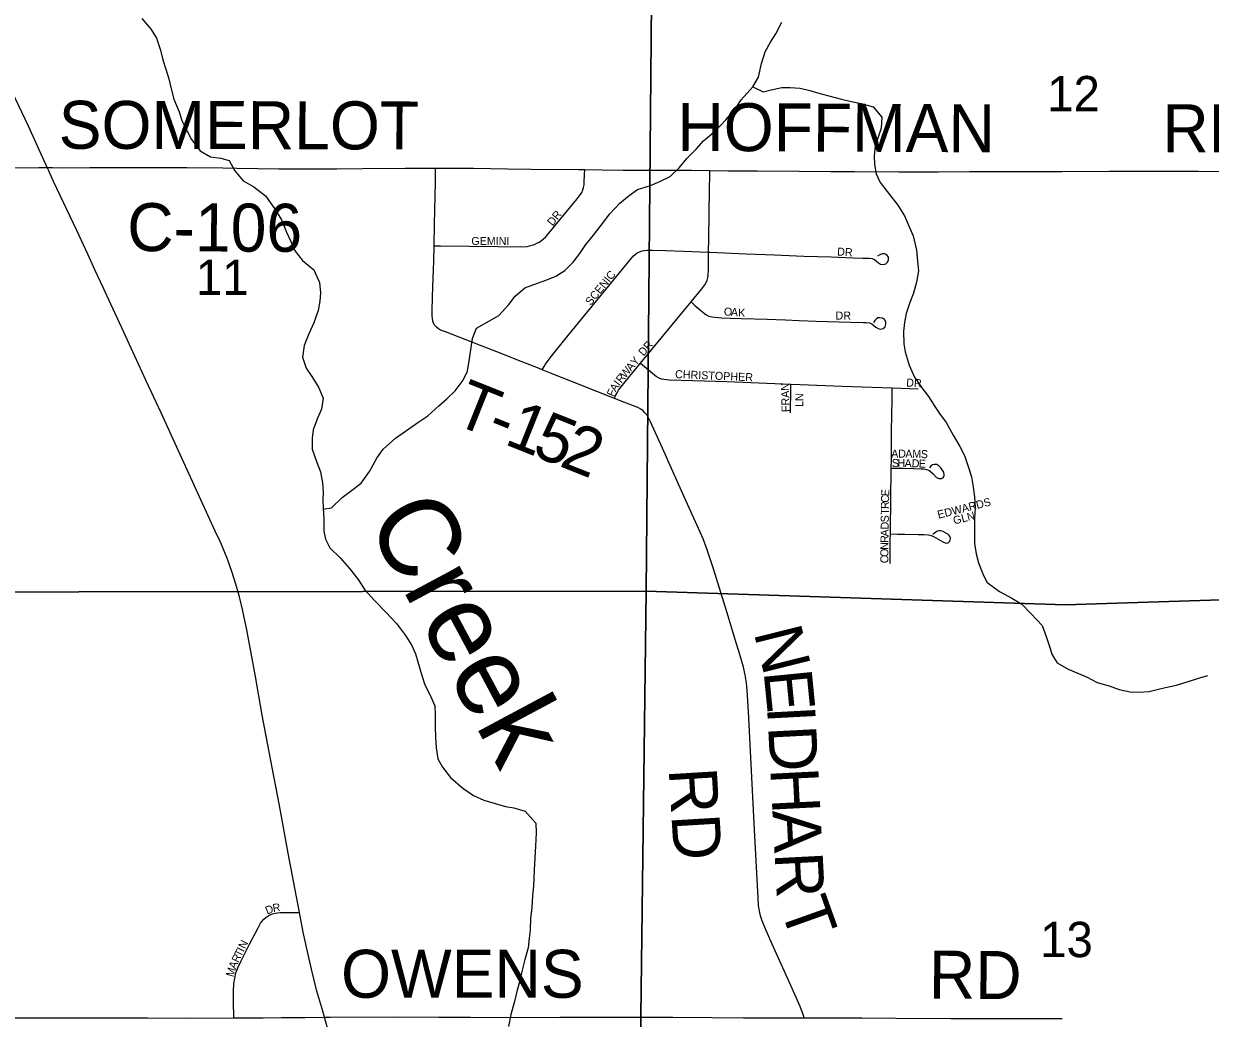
# Model space of a CAD drawing. Extents: x -9.1 to 34, y -3.1 to 22.
# Drawn here: x 6.461 to 7.865, y 15.245 to 16.422 of the extents above; entities that cross this region are included whole.
import ezdxf

# ---------------------------------------------------------------- set-up
doc = ezdxf.new("R2010")
doc.units = 0
for name, color, linetype in [('GM_X_County_Road', 7, 'Continuous'), ('GM_X_County_Road_Text', 7, 'Continuous'), ('GM_X_Minor_River', 7, 'Continuous'), ('GM_X_Minor_River_Text', 7, 'Continuous'), ('GM_X_Section', 7, 'Continuous'), ('GM_X_Section_Text', 7, 'Continuous'), ('GM_X_State_Route', 7, 'Continuous'), ('GM_X_Township_Road', 7, 'Continuous'), ('GM_X_Township_Road_Text', 7, 'Continuous'), ('GM_X_Township_Subdivision', 7, 'Continuous'), ('GM_X_Township_Subdivision_Text', 7, 'Continuous')]:
    doc.layers.add(name, color=color, linetype=linetype)

msp = doc.modelspace()

# ---------------------------------------------------------------- linework, layer by layer
at = {"layer": 'GM_X_County_Road'}
for points in [[(6.4495, 16.2516), (6.4791, 16.2519), (6.4892, 16.2518)], [(6.4892, 16.2518), (6.4954, 16.2517), (6.5082, 16.2516)], [(6.5082, 16.2516), (6.5082, 16.2516), (6.5394, 16.2518), (6.5643, 16.2519), (6.5953, 16.2519), (6.6544, 16.2518), (6.697, 16.2514)], [(6.697, 16.2514), (6.7134, 16.2512), (6.7632, 16.2505), (6.7943, 16.2503), (6.8316, 16.2505), (6.8626, 16.2507), (6.9124, 16.2513), (6.9372, 16.2512), (6.9485, 16.2512)], [(6.9485, 16.2512), (6.9932, 16.251), (7.0336, 16.2503), (7.0615, 16.25), (7.1175, 16.2495), (7.125, 16.2494)], [(7.125, 16.2494), (7.1454, 16.249), (7.1703, 16.2489), (7.2138, 16.2489), (7.2511, 16.2486), (7.2729, 16.2483)], [(7.2729, 16.2483), (7.2946, 16.248), (7.3288, 16.2479), (7.3785, 16.2474), (7.4159, 16.2473), (7.4438, 16.2471), (7.4967, 16.2468), (7.5433, 16.2469), (7.5806, 16.2471), (7.6148, 16.2473), (7.6459, 16.2472), (7.6894, 16.2473), (7.7453, 16.2476), (7.7764, 16.2474), (7.8199, 16.2477), (7.851, 16.2477), (7.9224, 16.2469), (7.9473, 16.2474), (7.9655, 16.2476)], [(5.9245, 15.2457), (5.9397, 15.2456), (5.9676, 15.2455), (5.9832, 15.2453), (6.0049, 15.2451), (6.0267, 15.2453), (6.0577, 15.2453), (6.1261, 15.245), (6.1758, 15.245), (6.2255, 15.2453), (6.2815, 15.2456), (6.3436, 15.2456), (6.3778, 15.2455), (6.4182, 15.2454), (6.4617, 15.2453), (6.5332, 15.2454), (6.6078, 15.2452), (6.6575, 15.245), (6.71, 15.2453)], [(6.71, 15.2453), (6.7445, 15.2455), (6.7663, 15.2457), (6.7942, 15.2457), (6.817, 15.246)], [(6.817, 15.246), (6.8242, 15.246), (6.8997, 15.2465), (6.9525, 15.2462), (6.9611, 15.2462)], [(6.9611, 15.2462), (6.9898, 15.246), (7.0426, 15.2459), (7.0954, 15.2463), (7.1389, 15.2462), (7.1917, 15.2463), (7.1944, 15.2463)], [(7.1944, 15.2463), (7.229, 15.246), (7.2756, 15.2458), (7.3128, 15.2454), (7.3377, 15.2454), (7.378, 15.2454), (7.3847, 15.2454)], [(7.3847, 15.2454), (7.4215, 15.2455), (7.4526, 15.2453), (7.4929, 15.2451), (7.5582, 15.2447), (7.6203, 15.2445), (7.6576, 15.2445), (7.6897, 15.2447)]]:
    msp.add_lwpolyline(points, dxfattribs=at)
at = {"layer": 'GM_X_Minor_River'}
for points in [[(6.6009, 16.4281), (6.6121, 16.4151), (6.6184, 16.4048), (6.6231, 16.3907), (6.626, 16.3793), (6.6296, 16.3682), (6.6328, 16.3568), (6.6357, 16.345), (6.6389, 16.3329), (6.6452, 16.3176), (6.6484, 16.3077), (6.6547, 16.2948), (6.6599, 16.2852), (6.6699, 16.2718), (6.6823, 16.2644), (6.6944, 16.2631), (6.7042, 16.26), (6.7109, 16.2481), (6.7209, 16.2362), (6.7337, 16.2292), (6.7472, 16.2184), (6.758, 16.2035), (6.7661, 16.1898), (6.7723, 16.1753), (6.7771, 16.1642), (6.7823, 16.1528), (6.7912, 16.1417), (6.8043, 16.1309), (6.8113, 16.1156), (6.8122, 16.1035), (6.8117, 16.0936), (6.8097, 16.0827), (6.8046, 16.068), (6.7987, 16.0551), (6.7932, 16.0412), (6.7911, 16.0272), (6.7955, 16.0143), (6.8022, 16.0047), (6.8099, 15.9917), (6.8154, 15.9787), (6.8134, 15.9659), (6.8087, 15.955), (6.8039, 15.9414), (6.8026, 15.9315), (6.8025, 15.9183), (6.8076, 15.9038), (6.8123, 15.8916), (6.8148, 15.8787), (6.8154, 15.8677), (6.8153, 15.8582), (6.8155, 15.8487), (6.8165, 15.8355), (6.8163, 15.8215), (6.8184, 15.8119), (6.8236, 15.8016), (6.8355, 15.7897), (6.8467, 15.7771), (6.8571, 15.7644), (6.8649, 15.7518), (6.8761, 15.7395), (6.8895, 15.7257), (6.9022, 15.7123), (6.913, 15.6981), (6.9204, 15.6862), (6.9248, 15.6763), (6.9274, 15.6668), (6.931, 15.6546), (6.9353, 15.6406), (6.9431, 15.6253), (6.9475, 15.6146), (6.9481, 15.6036), (6.9479, 15.5904), (6.9484, 15.5771)], [(6.8156, 15.8473), (6.8254, 15.849), (6.838, 15.8613), (6.8476, 15.8684), (6.8606, 15.8784), (6.8703, 15.892), (6.8792, 15.9078), (6.8866, 15.9186), (6.9011, 15.9317), (6.9168, 15.9425), (6.9287, 15.9507), (6.9394, 15.9581), (6.9524, 15.9697), (6.962, 15.9782), (6.9716, 15.9876), (6.9813, 16), (6.9863, 16.0109), (6.9884, 16.023), (6.9901, 16.0362), (6.9922, 16.0495), (6.9969, 16.0619), (7.0125, 16.0704), (7.0232, 16.0767), (7.0352, 16.0898), (7.0425, 16.0996), (7.054, 16.1096), (7.0692, 16.1151), (7.0803, 16.1191), (7.0909, 16.1231), (7.1016, 16.1298), (7.1112, 16.1399), (7.1193, 16.15), (7.1263, 16.1609), (7.1352, 16.1718), (7.1471, 16.1872), (7.1548, 16.1969), (7.1664, 16.2097), (7.1775, 16.2186), (7.1874, 16.2257), (7.2027, 16.2304), (7.2137, 16.2352), (7.2259, 16.2414), (7.2367, 16.2515), (7.2459, 16.2624), (7.2567, 16.2736), (7.2655, 16.2833), (7.2801, 16.2956), (7.292, 16.3084), (7.3024, 16.3207), (7.3101, 16.332), (7.324, 16.3473), (7.3306, 16.359), (7.3342, 16.3749), (7.3386, 16.3888), (7.3448, 16.4001), (7.351, 16.4103), (7.358, 16.4238)], [(7.324, 16.3473), (7.336, 16.3415), (7.3455, 16.344), (7.3581, 16.3465), (7.3679, 16.3467), (7.38, 16.3458), (7.3914, 16.343), (7.4019, 16.3398), (7.4136, 16.3366), (7.4287, 16.3326), (7.4385, 16.3306), (7.4521, 16.3278), (7.4661, 16.3238), (7.4765, 16.3115), (7.4756, 16.2986), (7.4724, 16.2888), (7.4685, 16.2771), (7.4675, 16.2658), (7.4678, 16.2555), (7.4699, 16.2445), (7.4743, 16.2342), (7.4855, 16.2201), (7.4955, 16.2074), (7.5033, 16.1948), (7.5092, 16.1807), (7.5136, 16.1712), (7.5175, 16.1541), (7.5188, 16.1411), (7.5198, 16.1294), (7.5174, 16.1162), (7.5138, 16.1033), (7.5094, 16.092), (7.5051, 16.0792), (7.5031, 16.0686), (7.5021, 16.0576), (7.5023, 16.0432), (7.5041, 16.0337), (7.5088, 16.0181), (7.515, 16.0036), (7.5236, 15.991), (7.5318, 15.981), (7.5384, 15.9703), (7.5447, 15.9608), (7.5525, 15.9501), (7.561, 15.9352), (7.5688, 15.9218), (7.5743, 15.9111), (7.5787, 15.8981), (7.5827, 15.8856), (7.5841, 15.8761), (7.5861, 15.862), (7.5867, 15.8491), (7.5862, 15.8363), (7.586, 15.8215), (7.5861, 15.8067), (7.5879, 15.7946), (7.5907, 15.7839), (7.5959, 15.7709), (7.6006, 15.761), (7.6156, 15.7502), (7.6303, 15.7421), (7.6419, 15.7351), (7.6528, 15.7239), (7.6662, 15.7097), (7.671, 15.6968), (7.6739, 15.6873), (7.6779, 15.6751), (7.6838, 15.6655), (7.6969, 15.6581), (7.709, 15.6531), (7.7195, 15.6487), (7.7312, 15.6425), (7.7455, 15.6385), (7.7572, 15.6342), (7.7704, 15.6314), (7.7806, 15.6308), (7.7928, 15.6318), (7.8053, 15.6347), (7.8156, 15.6372), (7.8251, 15.6393), (7.8388, 15.6433), (7.8525, 15.6477), (7.862, 15.6506)], [(6.9484, 15.5771), (6.9494, 15.5649), (6.9511, 15.552), (6.9567, 15.5421), (6.966, 15.5299), (6.9806, 15.5171), (6.9933, 15.5086), (7.0057, 15.5032), (7.0189, 15.4992), (7.0314, 15.4956), (7.0412, 15.4939), (7.0544, 15.49), (7.0671, 15.4758), (7.0677, 15.4644), (7.0667, 15.4485), (7.0658, 15.4349), (7.0652, 15.4201), (7.0642, 15.4015), (7.0633, 15.3902), (7.0623, 15.3754), (7.061, 15.3633), (7.0604, 15.3493), (7.0591, 15.3395), (7.0582, 15.3281), (7.0542, 15.3145), (7.0506, 15.3002), (7.0478, 15.2881), (7.0446, 15.2764), (7.0418, 15.2647), (7.0374, 15.2492), (7.0346, 15.2352)]]:
    msp.add_lwpolyline(points, dxfattribs=at)
at = {"layer": 'GM_X_Section'}
for points in [[(6.2011, 16.7548), (7.2066, 16.7532), (7.1977, 15.7504), (6.1904, 15.7491)], [(7.2066, 16.7532), (8.2139, 16.745), (8.1957, 15.7506), (7.6939, 15.7344), (7.1977, 15.7504)], [(6.1904, 15.7491), (7.1977, 15.7504), (7.1851, 14.7442), (6.1603, 14.7464)], [(7.1977, 15.7504), (7.6939, 15.7344), (8.1957, 15.7506), (8.1958, 15.7211), (8.1871, 14.738), (7.1851, 14.7442)]]:
    msp.add_lwpolyline(points, close=True, dxfattribs=at)
at = {"layer": 'GM_X_State_Route'}
msp.add_lwpolyline([(6.8254, 15.2156), (6.817, 15.246), (6.815, 15.2531), (6.808, 15.277), (6.8017, 15.303), (6.795, 15.3325), (6.7918, 15.3469), (6.7874, 15.3701), (6.7742, 15.4404), (6.7637, 15.4968), (6.7533, 15.5518), (6.7435, 15.6037), (6.7353, 15.6496), (6.7251, 15.7046), (6.7201, 15.7289), (6.7164, 15.7439), (6.7121, 15.7588), (6.7074, 15.7736), (6.7022, 15.7882), (6.6952, 15.8055), (6.692, 15.8126), (6.6905, 15.8157), (6.6879, 15.8214), (6.6548, 15.8942), (6.6237, 15.9616), (6.6057, 16), (6.5885, 16.038), (6.5774, 16.0622), (6.5643, 16.0902), (6.5552, 16.1099), (6.5456, 16.1306), (6.537, 16.1492), (6.524, 16.1774), (6.4967, 16.2355), (6.4909, 16.248), (6.4892, 16.2518), (6.4875, 16.2555), (6.4668, 16.3007), (6.4474, 16.3421)], dxfattribs=at)
at = {"layer": 'GM_X_Township_Road'}
for points in [[(6.9467, 16.1591), (6.9473, 16.1849), (6.9486, 16.2346), (6.9485, 16.244), (6.9485, 16.2512)], [(7.0746, 16.0124), (7.0701, 16.0143), (7.0499, 16.0223), (7.0211, 16.0338), (7.0037, 16.0406), (6.9834, 16.0483), (6.9602, 16.0572), (6.9545, 16.0595), (6.9519, 16.061), (6.9496, 16.0628), (6.9477, 16.065), (6.9462, 16.0675), (6.9452, 16.0702), (6.9447, 16.0732), (6.9444, 16.0762), (6.9444, 16.0823), (6.945, 16.0979), (6.9453, 16.1103), (6.9463, 16.1414), (6.9467, 16.1591)], [(7.1601, 15.9786), (7.1393, 15.9867), (7.1104, 15.9981), (7.0844, 16.0083), (7.0746, 16.0124)], [(7.3847, 15.2454), (7.3837, 15.2481), (7.3797, 15.2588), (7.3688, 15.2836), (7.3484, 15.3289), (7.3396, 15.3488), (7.3349, 15.3603), (7.333, 15.3661), (7.3317, 15.3721), (7.3307, 15.3782), (7.33, 15.3874), (7.3259, 15.4681), (7.3186, 15.6078), (7.3172, 15.6327), (7.3162, 15.642), (7.3147, 15.6513), (7.3126, 15.6604), (7.3085, 15.6754), (7.303, 15.6933), (7.2931, 15.7259), (7.2773, 15.7768), (7.2694, 15.8007), (7.265, 15.8123), (7.258, 15.8281), (7.2447, 15.8577), (7.2292, 15.892), (7.2169, 15.9196), (7.2029, 15.9509), (7.2, 15.9564), (7.1983, 15.9591), (7.1962, 15.9616), (7.1939, 15.9639), (7.1913, 15.9658), (7.1886, 15.9674), (7.1857, 15.9687), (7.1711, 15.9743), (7.1601, 15.9786)]]:
    msp.add_lwpolyline(points, dxfattribs=at)
at = {"layer": 'GM_X_Township_Subdivision'}
for points in [[(6.9467, 16.1591), (6.9543, 16.159), (6.9885, 16.1586), (7.0226, 16.1583), (7.0505, 16.1581), (7.0567, 16.1585), (7.0598, 16.159), (7.0628, 16.1598), (7.0657, 16.1609), (7.0685, 16.1622), (7.0712, 16.1637), (7.0737, 16.1655), (7.0761, 16.1674), (7.0784, 16.1696), (7.0806, 16.1718), (7.116, 16.215), (7.1199, 16.2199), (7.1215, 16.2225), (7.1228, 16.2253), (7.1236, 16.2283), (7.1242, 16.2313), (7.1244, 16.2344), (7.1248, 16.2437), (7.125, 16.2494)], [(7.2715, 16.1516), (7.2718, 16.1678), (7.2725, 16.2268), (7.2728, 16.2423), (7.2729, 16.2483)], [(7.0746, 16.0124), (7.0769, 16.0165), (7.0785, 16.0192), (7.0839, 16.0267), (7.1013, 16.0485), (7.1212, 16.0725), (7.141, 16.0964), (7.1626, 16.1228), (7.1823, 16.1468), (7.1846, 16.1489), (7.1871, 16.1507), (7.1899, 16.1521), (7.1928, 16.1531), (7.1958, 16.1537), (7.1989, 16.1541), (7.2051, 16.1541), (7.2205, 16.1535), (7.2422, 16.1527), (7.2715, 16.1516)], [(7.251, 16.0929), (7.2636, 16.1083), (7.2671, 16.1132), (7.2685, 16.1159), (7.2697, 16.1186), (7.2704, 16.1215), (7.2709, 16.1245), (7.2713, 16.1306), (7.2715, 16.1516)], [(7.2715, 16.1516), (7.2731, 16.1515), (7.3158, 16.1496), (7.3494, 16.1487), (7.3841, 16.1471), (7.4165, 16.146), (7.4424, 16.1448), (7.454, 16.1447), (7.4613, 16.1445), (7.465, 16.1441), (7.4676, 16.143), (7.4723, 16.1389), (7.475, 16.1374), (7.4781, 16.1369), (7.481, 16.1378), (7.4833, 16.1398), (7.4844, 16.1427), (7.4842, 16.1458), (7.4825, 16.1484), (7.4799, 16.1499), (7.4768, 16.1499), (7.474, 16.1487), (7.4714, 16.147)], [(7.191, 16.0203), (7.2024, 16.034), (7.2341, 16.0723), (7.251, 16.0929)], [(7.251, 16.0929), (7.2554, 16.0886), (7.2575, 16.0865), (7.2623, 16.0825), (7.2641, 16.0809), (7.267, 16.0788), (7.2691, 16.0775), (7.2718, 16.0761), (7.2755, 16.0751), (7.2792, 16.0748), (7.2871, 16.074), (7.2975, 16.0736), (7.3104, 16.073), (7.3408, 16.0724), (7.3623, 16.0715), (7.3787, 16.0709), (7.3986, 16.0702), (7.4393, 16.069), (7.4544, 16.0686), (7.4581, 16.0686), (7.4617, 16.0682), (7.4645, 16.0669), (7.4693, 16.0629), (7.472, 16.0614), (7.4751, 16.0607), (7.478, 16.0613), (7.4802, 16.0634), (7.4813, 16.0663), (7.4812, 16.0694), (7.4796, 16.072), (7.4771, 16.0737), (7.474, 16.0741), (7.4719, 16.0738), (7.47, 16.0729), (7.4681, 16.0708), (7.4667, 16.0686)], [(7.1601, 15.9786), (7.1611, 15.9811), (7.1632, 15.9852), (7.1651, 15.9883), (7.1727, 15.9982), (7.191, 16.0203)], [(7.191, 16.0203), (7.198, 16.0144), (7.2051, 16.0084), (7.2099, 16.0045), (7.2126, 16.003), (7.2155, 16.0019), (7.2185, 16.0013), (7.2247, 16.0007), (7.2527, 15.9997), (7.293, 15.9984), (7.3687, 15.9955)], [(7.3683, 15.9614), (7.3684, 15.9678), (7.3688, 15.9837), (7.3687, 15.9869), (7.3687, 15.99), (7.3687, 15.9955)], [(7.3687, 15.9955), (7.38, 15.995), (7.4296, 15.9931), (7.4888, 15.991)], [(7.4875, 15.8959), (7.4877, 15.9064), (7.488, 15.9393), (7.4884, 15.959), (7.4888, 15.9768), (7.4888, 15.9876), (7.4888, 15.991)], [(7.4888, 15.991), (7.5196, 15.9899)], [(7.4865, 15.8182), (7.4867, 15.8295), (7.4869, 15.8525), (7.487, 15.8662), (7.4873, 15.8878), (7.4875, 15.8959)], [(7.4875, 15.8959), (7.4921, 15.8959), (7.5017, 15.8959), (7.5138, 15.8956), (7.5229, 15.8954), (7.526, 15.8952), (7.5291, 15.8944), (7.532, 15.8935), (7.5346, 15.8916), (7.5369, 15.8896), (7.5413, 15.885), (7.544, 15.8836), (7.547, 15.8837), (7.5494, 15.8855), (7.5503, 15.8873), (7.5503, 15.8883), (7.5496, 15.8913), (7.548, 15.894), (7.5462, 15.8965), (7.5439, 15.8987), (7.5414, 15.9002), (7.5384, 15.9004), (7.5362, 15.8998), (7.5345, 15.8984), (7.5328, 15.8965)], [(7.4865, 15.8182), (7.4952, 15.818), (7.5036, 15.8179), (7.5193, 15.8176), (7.5262, 15.8176), (7.5318, 15.8171), (7.5348, 15.8163), (7.5377, 15.8151), (7.5485, 15.8087), (7.5514, 15.8075), (7.5527, 15.8072), (7.5548, 15.8078), (7.5567, 15.8095), (7.5573, 15.811), (7.5577, 15.8127), (7.5573, 15.8149), (7.5559, 15.8162), (7.5544, 15.8177), (7.5517, 15.8194), (7.5489, 15.8209), (7.546, 15.822), (7.545, 15.822), (7.5442, 15.822), (7.5424, 15.8215), (7.5405, 15.8203), (7.5388, 15.8191), (7.5368, 15.8174)], [(7.4861, 15.7831), (7.4861, 15.7862), (7.4861, 15.8112), (7.4865, 15.8182)], [(6.71, 15.2453), (6.7099, 15.2486), (6.7095, 15.2612), (6.7094, 15.2768), (6.7099, 15.2862), (6.7109, 15.2924), (6.7124, 15.2985), (6.7145, 15.3044), (6.7184, 15.313), (6.7285, 15.3325), (6.7385, 15.352), (6.7415, 15.3575), (6.7433, 15.36), (6.7454, 15.3623), (6.7478, 15.3642), (6.7504, 15.366), (6.753, 15.3674), (6.7557, 15.3685), (6.7586, 15.3693), (6.7617, 15.3697), (6.7648, 15.37), (6.7711, 15.37), (6.7874, 15.3701)]]:
    msp.add_lwpolyline(points, dxfattribs=at)

# ---------------------------------------------------------------- texts
at = {"layer": 'GM_X_County_Road_Text'}
for s, rotation, p in [('SOMERLOT', 359.8757, (6.5026, 16.2741)), ('HOFFMAN', 359.7204, (7.2344, 16.2716)), ('RD', 0, (7.8083, 16.2699)), ('C-106', 359.7271, (6.5836, 16.153)), ('OWENS', 0, (6.8367, 15.2691)), ('RD', 359.5457, (7.5319, 15.2683))]:
    msp.add_text(s, height=0.05682, rotation=rotation, dxfattribs=at).set_placement(p)
at = {"layer": 'GM_X_Minor_River_Text'}
msp.add_text('Creek', height=0.09471, rotation=298.147, dxfattribs=at).set_placement((6.8655, 15.8343))
at = {"layer": 'GM_X_Section_Text'}
for s, p in [('12', (7.6721, 16.3184)), ('11', (6.665, 16.101)), ('13', (7.6638, 15.3172))]:
    msp.add_text(s, height=0.04186, rotation=0, dxfattribs=at).set_placement(p)
at = {"layer": 'GM_X_Township_Road_Text'}
for s, height, rotation, p in [('T', 0.0568, 338.1994, (6.9672, 15.9495)), ('1', 0.0568, 338.2056, (7.0284, 15.925)), ('5', 0.0568, 338.2116, (7.0609, 15.912)), ('-', 0.0568, 338.1913, (7.0067, 15.9337)), ('2', 0.0568, 338.2795, (7.0934, 15.899)), ('N', 0.0568, 284.0142, (7.3247, 15.7016)), ('E', 0.0568, 275.6492, (7.3365, 15.6553)), ('I', 0.0568, 273.0456, (7.3406, 15.6137)), ('D', 0.0568, 272.9264, (7.3419, 15.5904)), ('RD', 0.05682, 273.4533, (7.2242, 15.54)), ('H', 0.0568, 272.9155, (7.3444, 15.5405)), ('A', 0.0568, 272.9119, (7.3469, 15.4905)), ('R', 0.0568, 273.0015, (7.3495, 15.4405)), ('T', 0.0568, 289.6445, (7.3555, 15.3763))]:
    msp.add_text(s, height=height, rotation=rotation, dxfattribs=at).set_placement(p)
at = {"layer": 'GM_X_Township_Subdivision_Text'}
for s, rotation, p in [('DR', 51.3366, (7.087, 16.182)), ('GEMINI', 0, (6.9908, 16.1602)), ('DR', 356.989, (7.4234, 16.1477)), ('SCENIC', 50.7924, (7.132, 16.0879)), ('O', 355.7337, (7.2893, 16.0769)), ('A', 355.7473, (7.2976, 16.0763)), ('K', 357.2792, (7.3062, 16.0756)), ('DR', 0, (7.4217, 16.0719)), ('DR', 48.8141, (7.1945, 16.028)), ('W', 50.3817, (7.173, 16.0018)), ('A', 50.2, (7.1799, 16.0101)), ('Y', 50.2067, (7.1853, 16.0165)), ('R', 51.8332, (7.1684, 15.9959)), ('CHRISTOPHER', 357.5903, (7.2317, 16.0027)), ('DR', 356.8222, (7.5051, 15.9927)), ('F', 66.3565, (7.1592, 15.9799)), ('A', 58.2078, (7.1617, 15.9857)), ('I', 53.1913, (7.166, 15.9926)), ('FRAN', 91.541, (7.3674, 15.9625)), ('LN', 90, (7.3835, 15.9684)), ('A', 359.6502, (7.4875, 15.9085)), ('D', 359.6437, (7.4958, 15.9085)), ('A', 359.6284, (7.5042, 15.9084)), ('M', 358.3785, (7.5124, 15.9084)), ('S', 0, (7.4883, 15.8973)), ('H', 359.9563, (7.495, 15.8973)), ('A', 359.2786, (7.5033, 15.8972)), ('D', 358.2511, (7.5116, 15.8971)), ('E', 357.0475, (7.5199, 15.8969)), ('S', 356.993, (7.5224, 15.9081)), ('C', 89.32, (7.4849, 15.8551)), ('E', 86.3095, (7.485, 15.8625)), ('T', 89.3044, (7.4847, 15.8409)), ('R', 89.3288, (7.4848, 15.8476)), ('EDWARDS', 14.2356, (7.5435, 15.8361)), ('S', 89.317, (7.4846, 15.8318)), ('GLN', 14.0362, (7.5621, 15.8293)), ('A', 89.317, (7.4844, 15.8151)), ('D', 89.3285, (7.4845, 15.8234)), ('N', 89.3224, (7.4842, 15.7993)), ('R', 89.3173, (7.4843, 15.8076)), ('C', 89.32, (7.4841, 15.7834)), ('O', 89.3285, (7.4841, 15.7909)), ('D', 22.0449, (6.7493, 15.3675)), ('R', 9.2188, (6.7565, 15.3705)), ('I', 63.3958, (6.7214, 15.3226)), ('N', 63.4347, (6.7232, 15.3263)), ('R', 63.6304, (6.7151, 15.3099)), ('T', 63.4349, (6.7184, 15.3166)), ('M', 73.5066, (6.7092, 15.2931)), ('A', 67.1229, (6.7119, 15.3024))]:
    msp.add_text(s, height=0.00947, rotation=rotation, dxfattribs=at).set_placement(p)

doc.saveas('drawing.dxf')
